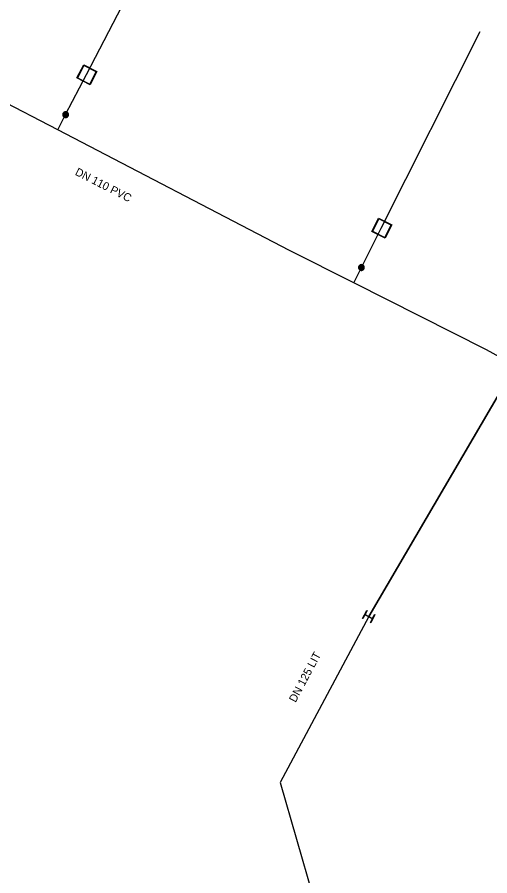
# Model space of a CAD drawing. Extents: x -818065 to -817466, y -1067968 to -1067520.
# Drawn here: x -817769.8 to -817728.5, y -1067828 to -1067753 of the extents above; entities that cross this region are included whole.
import ezdxf

# ---------------------------------------------------------------- set-up
doc = ezdxf.new("R2010")
doc.units = 0
doc.layers.add('Default', color=7, linetype='Continuous')
doc.layers.add('Level 0', color=7, linetype='Continuous')

msp = doc.modelspace()

# ---------------------------------------------------------------- linework, layer by layer
at = {"layer": 'Default'}
for points in [[(-817764.005, -1067757.155), (-817762.847, -1067757.745), (-817763.437, -1067758.903), (-817764.596, -1067758.313), (-817764.005, -1067757.155)], [(-817764.541, -1067758.295), (-817763.455, -1067758.849), (-817762.902, -1067757.763), (-817763.988, -1067757.209), (-817764.541, -1067758.295)], [(-817738.211, -1067770.573), (-817737.053, -1067771.163), (-817737.643, -1067772.321), (-817738.801, -1067771.731), (-817738.211, -1067770.573)], [(-817738.747, -1067771.713), (-817737.661, -1067772.267), (-817737.107, -1067771.181), (-817738.193, -1067770.627), (-817738.747, -1067771.713)], [(-817739.399, -1067805.223), (-817739.581, -1067805.565), (-817739.603, -1067805.554), (-817739.228, -1067804.847), (-817739.206, -1067804.859), (-817739.388, -1067805.201), (-817738.725, -1067805.553), (-817738.543, -1067805.211), (-817738.521, -1067805.223), (-817738.897, -1067805.929), (-817738.919, -1067805.917), (-817738.737, -1067805.575), (-817739.399, -1067805.223)]]:
    msp.add_lwpolyline(points, dxfattribs=at)
for points in [[(-817765.584, -1067761.269), (-817765.521, -1067761.269), (-817765.461, -1067761.301), (-817765.402, -1067761.334), (-817765.368, -1067761.394), (-817765.334, -1067761.454), (-817765.334, -1067761.519), (-817765.334, -1067761.584), (-817765.367, -1067761.644), (-817765.4, -1067761.703), (-817765.459, -1067761.736), (-817765.519, -1067761.769), (-817765.584, -1067761.769), (-817765.649, -1067761.769), (-817765.708, -1067761.736), (-817765.768, -1067761.703), (-817765.801, -1067761.644), (-817765.834, -1067761.584), (-817765.834, -1067761.519), (-817765.834, -1067761.454), (-817765.8, -1067761.394), (-817765.767, -1067761.334), (-817765.707, -1067761.301), (-817765.647, -1067761.269), (-817765.584, -1067761.269)], [(-817765.584, -1067761.293), (-817765.641, -1067761.293), (-817765.696, -1067761.322), (-817765.75, -1067761.351), (-817765.78, -1067761.405), (-817765.81, -1067761.46), (-817765.81, -1067761.519), (-817765.81, -1067761.578), (-817765.781, -1067761.632), (-817765.751, -1067761.686), (-817765.697, -1067761.716), (-817765.643, -1067761.746), (-817765.584, -1067761.746), (-817765.525, -1067761.746), (-817765.471, -1067761.716), (-817765.417, -1067761.686), (-817765.387, -1067761.632), (-817765.357, -1067761.578), (-817765.357, -1067761.519), (-817765.357, -1067761.46), (-817765.388, -1067761.405), (-817765.419, -1067761.351), (-817765.473, -1067761.322), (-817765.527, -1067761.293), (-817765.584, -1067761.293)], [(-817765.584, -1067761.31), (-817765.531, -1067761.31), (-817765.481, -1067761.337), (-817765.431, -1067761.364), (-817765.403, -1067761.414), (-817765.374, -1067761.464), (-817765.374, -1067761.519), (-817765.374, -1067761.574), (-817765.402, -1067761.624), (-817765.429, -1067761.673), (-817765.479, -1067761.701), (-817765.529, -1067761.729), (-817765.584, -1067761.729), (-817765.638, -1067761.729), (-817765.688, -1067761.701), (-817765.738, -1067761.673), (-817765.766, -1067761.624), (-817765.793, -1067761.574), (-817765.793, -1067761.519), (-817765.793, -1067761.464), (-817765.765, -1067761.414), (-817765.737, -1067761.364), (-817765.687, -1067761.337), (-817765.637, -1067761.31), (-817765.584, -1067761.31)], [(-817765.584, -1067761.332), (-817765.663, -1067761.332), (-817765.717, -1067761.387), (-817765.771, -1067761.441), (-817765.771, -1067761.519), (-817765.771, -1067761.597), (-817765.717, -1067761.652), (-817765.662, -1067761.707), (-817765.584, -1067761.707), (-817765.506, -1067761.707), (-817765.451, -1067761.652), (-817765.396, -1067761.597), (-817765.396, -1067761.519), (-817765.396, -1067761.441), (-817765.451, -1067761.387), (-817765.506, -1067761.332), (-817765.584, -1067761.332)], [(-817765.584, -1067761.355), (-817765.516, -1067761.355), (-817765.468, -1067761.403), (-817765.42, -1067761.451), (-817765.42, -1067761.519), (-817765.42, -1067761.587), (-817765.468, -1067761.635), (-817765.516, -1067761.683), (-817765.584, -1067761.683), (-817765.653, -1067761.683), (-817765.701, -1067761.635), (-817765.748, -1067761.587), (-817765.748, -1067761.519), (-817765.748, -1067761.451), (-817765.701, -1067761.403), (-817765.653, -1067761.355), (-817765.584, -1067761.355)], [(-817765.584, -1067761.374), (-817765.644, -1067761.374), (-817765.687, -1067761.417), (-817765.729, -1067761.459), (-817765.729, -1067761.519), (-817765.729, -1067761.578), (-817765.687, -1067761.621), (-817765.644, -1067761.663), (-817765.584, -1067761.663), (-817765.525, -1067761.663), (-817765.482, -1067761.621), (-817765.44, -1067761.578), (-817765.44, -1067761.519), (-817765.44, -1067761.459), (-817765.482, -1067761.417), (-817765.524, -1067761.374), (-817765.584, -1067761.374)], [(-817765.584, -1067761.394), (-817765.532, -1067761.394), (-817765.495, -1067761.431), (-817765.459, -1067761.467), (-817765.459, -1067761.519), (-817765.459, -1067761.571), (-817765.496, -1067761.608), (-817765.532, -1067761.644), (-817765.584, -1067761.644), (-817765.636, -1067761.644), (-817765.672, -1067761.608), (-817765.709, -1067761.571), (-817765.709, -1067761.519), (-817765.709, -1067761.467), (-817765.673, -1067761.431), (-817765.636, -1067761.394), (-817765.584, -1067761.394)], [(-817765.584, -1067761.417), (-817765.626, -1067761.417), (-817765.656, -1067761.447), (-817765.686, -1067761.477), (-817765.686, -1067761.519), (-817765.686, -1067761.561), (-817765.656, -1067761.591), (-817765.626, -1067761.62), (-817765.584, -1067761.62), (-817765.542, -1067761.62), (-817765.512, -1067761.591), (-817765.483, -1067761.561), (-817765.483, -1067761.519), (-817765.483, -1067761.477), (-817765.512, -1067761.447), (-817765.542, -1067761.417), (-817765.584, -1067761.417)], [(-817765.584, -1067761.435), (-817765.549, -1067761.435), (-817765.524, -1067761.459), (-817765.5, -1067761.484), (-817765.5, -1067761.519), (-817765.5, -1067761.554), (-817765.525, -1067761.579), (-817765.549, -1067761.603), (-817765.584, -1067761.603), (-817765.619, -1067761.603), (-817765.644, -1067761.579), (-817765.668, -1067761.554), (-817765.668, -1067761.519), (-817765.668, -1067761.484), (-817765.644, -1067761.459), (-817765.619, -1067761.435), (-817765.584, -1067761.435)], [(-817765.584, -1067761.457), (-817765.61, -1067761.457), (-817765.628, -1067761.475), (-817765.646, -1067761.493), (-817765.646, -1067761.519), (-817765.646, -1067761.545), (-817765.628, -1067761.563), (-817765.61, -1067761.582), (-817765.584, -1067761.582), (-817765.558, -1067761.582), (-817765.54, -1067761.563), (-817765.521, -1067761.545), (-817765.521, -1067761.519), (-817765.521, -1067761.493), (-817765.54, -1067761.475), (-817765.558, -1067761.457), (-817765.584, -1067761.457)], [(-817765.584, -1067761.48), (-817765.568, -1067761.48), (-817765.556, -1067761.491), (-817765.545, -1067761.503), (-817765.545, -1067761.519), (-817765.545, -1067761.535), (-817765.556, -1067761.547), (-817765.568, -1067761.558), (-817765.584, -1067761.558), (-817765.6, -1067761.558), (-817765.612, -1067761.547), (-817765.623, -1067761.535), (-817765.623, -1067761.519), (-817765.623, -1067761.503), (-817765.612, -1067761.491), (-817765.6, -1067761.48), (-817765.584, -1067761.48)], [(-817765.584, -1067761.496), (-817765.594, -1067761.496), (-817765.601, -1067761.502), (-817765.608, -1067761.509), (-817765.608, -1067761.519), (-817765.608, -1067761.529), (-817765.601, -1067761.536), (-817765.594, -1067761.543), (-817765.584, -1067761.543), (-817765.574, -1067761.543), (-817765.567, -1067761.536), (-817765.561, -1067761.529), (-817765.561, -1067761.519), (-817765.561, -1067761.509), (-817765.567, -1067761.502), (-817765.574, -1067761.496), (-817765.584, -1067761.496)], [(-817739.708, -1067774.628), (-817739.645, -1067774.628), (-817739.585, -1067774.66), (-817739.525, -1067774.692), (-817739.491, -1067774.752), (-817739.457, -1067774.812), (-817739.457, -1067774.878), (-817739.457, -1067774.943), (-817739.49, -1067775.002), (-817739.523, -1067775.062), (-817739.583, -1067775.095), (-817739.642, -1067775.128), (-817739.708, -1067775.128), (-817739.772, -1067775.128), (-817739.832, -1067775.095), (-817739.891, -1067775.062), (-817739.924, -1067775.002), (-817739.957, -1067774.943), (-817739.957, -1067774.878), (-817739.957, -1067774.812), (-817739.924, -1067774.752), (-817739.89, -1067774.692), (-817739.831, -1067774.66), (-817739.771, -1067774.628), (-817739.708, -1067774.628)], [(-817739.708, -1067774.651), (-817739.765, -1067774.651), (-817739.819, -1067774.68), (-817739.873, -1067774.709), (-817739.904, -1067774.764), (-817739.934, -1067774.819), (-817739.934, -1067774.878), (-817739.934, -1067774.937), (-817739.904, -1067774.991), (-817739.874, -1067775.044), (-817739.82, -1067775.074), (-817739.766, -1067775.104), (-817739.708, -1067775.104), (-817739.649, -1067775.104), (-817739.594, -1067775.074), (-817739.54, -1067775.044), (-817739.511, -1067774.991), (-817739.481, -1067774.937), (-817739.481, -1067774.878), (-817739.481, -1067774.819), (-817739.512, -1067774.764), (-817739.542, -1067774.709), (-817739.596, -1067774.68), (-817739.65, -1067774.651), (-817739.708, -1067774.651)], [(-817739.708, -1067774.668), (-817739.655, -1067774.668), (-817739.605, -1067774.695), (-817739.555, -1067774.722), (-817739.526, -1067774.773), (-817739.498, -1067774.823), (-817739.498, -1067774.878), (-817739.498, -1067774.932), (-817739.525, -1067774.982), (-817739.553, -1067775.032), (-817739.603, -1067775.06), (-817739.653, -1067775.087), (-817739.708, -1067775.087), (-817739.762, -1067775.087), (-817739.812, -1067775.06), (-817739.862, -1067775.032), (-817739.889, -1067774.982), (-817739.917, -1067774.932), (-817739.917, -1067774.878), (-817739.917, -1067774.823), (-817739.889, -1067774.773), (-817739.861, -1067774.722), (-817739.811, -1067774.695), (-817739.76, -1067774.668), (-817739.708, -1067774.668)], [(-817739.708, -1067774.69), (-817739.786, -1067774.69), (-817739.84, -1067774.745), (-817739.895, -1067774.8), (-817739.895, -1067774.878), (-817739.895, -1067774.956), (-817739.84, -1067775.01), (-817739.785, -1067775.065), (-817739.708, -1067775.065), (-817739.63, -1067775.065), (-817739.575, -1067775.01), (-817739.52, -1067774.956), (-817739.52, -1067774.878), (-817739.52, -1067774.8), (-817739.574, -1067774.745), (-817739.629, -1067774.69), (-817739.708, -1067774.69)], [(-817739.708, -1067774.713), (-817739.639, -1067774.713), (-817739.592, -1067774.761), (-817739.544, -1067774.809), (-817739.544, -1067774.877), (-817739.544, -1067774.945), (-817739.592, -1067774.993), (-817739.64, -1067775.041), (-817739.708, -1067775.041), (-817739.776, -1067775.041), (-817739.824, -1067774.993), (-817739.872, -1067774.945), (-817739.872, -1067774.877), (-817739.872, -1067774.809), (-817739.824, -1067774.761), (-817739.776, -1067774.713), (-817739.708, -1067774.713)], [(-817739.708, -1067774.733), (-817739.768, -1067774.733), (-817739.81, -1067774.775), (-817739.852, -1067774.817), (-817739.852, -1067774.877), (-817739.852, -1067774.937), (-817739.81, -1067774.979), (-817739.768, -1067775.021), (-817739.708, -1067775.021), (-817739.648, -1067775.021), (-817739.606, -1067774.979), (-817739.564, -1067774.937), (-817739.564, -1067774.877), (-817739.564, -1067774.817), (-817739.606, -1067774.775), (-817739.648, -1067774.733), (-817739.708, -1067774.733)], [(-817739.708, -1067774.753), (-817739.655, -1067774.753), (-817739.619, -1067774.789), (-817739.582, -1067774.826), (-817739.582, -1067774.878), (-817739.582, -1067774.93), (-817739.619, -1067774.966), (-817739.656, -1067775.003), (-817739.708, -1067775.003), (-817739.759, -1067775.003), (-817739.796, -1067774.966), (-817739.832, -1067774.93), (-817739.832, -1067774.878), (-817739.832, -1067774.826), (-817739.796, -1067774.789), (-817739.76, -1067774.753), (-817739.708, -1067774.753)], [(-817739.708, -1067774.776), (-817739.75, -1067774.776), (-817739.78, -1067774.806), (-817739.809, -1067774.835), (-817739.809, -1067774.877), (-817739.809, -1067774.92), (-817739.78, -1067774.949), (-817739.75, -1067774.979), (-817739.708, -1067774.979), (-817739.666, -1067774.979), (-817739.636, -1067774.949), (-817739.606, -1067774.92), (-817739.606, -1067774.877), (-817739.606, -1067774.835), (-817739.636, -1067774.806), (-817739.665, -1067774.776), (-817739.708, -1067774.776)], [(-817739.708, -1067774.793), (-817739.672, -1067774.793), (-817739.648, -1067774.818), (-817739.623, -1067774.842), (-817739.623, -1067774.877), (-817739.623, -1067774.913), (-817739.648, -1067774.937), (-817739.673, -1067774.962), (-817739.708, -1067774.962), (-817739.743, -1067774.962), (-817739.767, -1067774.937), (-817739.792, -1067774.913), (-817739.792, -1067774.877), (-817739.792, -1067774.842), (-817739.767, -1067774.818), (-817739.743, -1067774.793), (-817739.708, -1067774.793)], [(-817739.708, -1067774.815), (-817739.733, -1067774.815), (-817739.752, -1067774.833), (-817739.77, -1067774.852), (-817739.77, -1067774.878), (-817739.77, -1067774.904), (-817739.752, -1067774.922), (-817739.733, -1067774.94), (-817739.708, -1067774.94), (-817739.681, -1067774.94), (-817739.663, -1067774.922), (-817739.645, -1067774.904), (-817739.645, -1067774.878), (-817739.645, -1067774.852), (-817739.663, -1067774.833), (-817739.681, -1067774.815), (-817739.708, -1067774.815)], [(-817739.708, -1067774.839), (-817739.691, -1067774.839), (-817739.68, -1067774.85), (-817739.669, -1067774.861), (-817739.669, -1067774.878), (-817739.669, -1067774.894), (-817739.68, -1067774.905), (-817739.691, -1067774.917), (-817739.708, -1067774.917), (-817739.724, -1067774.917), (-817739.735, -1067774.905), (-817739.747, -1067774.894), (-817739.747, -1067774.878), (-817739.747, -1067774.861), (-817739.735, -1067774.85), (-817739.724, -1067774.839), (-817739.708, -1067774.839)], [(-817739.708, -1067774.854), (-817739.717, -1067774.854), (-817739.724, -1067774.861), (-817739.731, -1067774.868), (-817739.731, -1067774.878), (-817739.731, -1067774.887), (-817739.724, -1067774.894), (-817739.717, -1067774.901), (-817739.708, -1067774.901), (-817739.698, -1067774.901), (-817739.691, -1067774.894), (-817739.684, -1067774.887), (-817739.684, -1067774.878), (-817739.684, -1067774.868), (-817739.691, -1067774.861), (-817739.698, -1067774.854), (-817739.708, -1067774.854)]]:
    msp.add_open_spline(points, degree=3, dxfattribs=at)
at = {"layer": 'Level 0'}
for p, q in [((-817763.763, -1067758.013), (-817751.347, -1067734.113)), ((-817737.968, -1067771.431), (-817729.305, -1067754.261)), ((-817765.584, -1067761.519), (-817763.763, -1067758.013)), ((-817766.276, -1067762.85), (-817773.173, -1067759.267)), ((-817766.276, -1067762.85), (-817765.584, -1067761.519)), ((-817746.009, -1067773.378), (-817766.276, -1067762.85)), ((-817739.708, -1067774.877), (-817737.968, -1067771.431)), ((-817740.383, -1067776.217), (-817746.009, -1067773.378)), ((-817740.383, -1067776.217), (-817739.708, -1067774.877)), ((-817728.777, -1067782.073), (-817740.383, -1067776.217)), ((-817724.16, -1067779.91), (-817739.07, -1067805.39)), ((-817739.07, -1067805.39), (-817724.16, -1067779.91)), ((-817727.322, -1067782.861), (-817728.777, -1067782.073)), ((-817739.07, -1067805.39), (-817746.81, -1067819.9)), ((-817746.81, -1067819.9), (-817741.25, -1067839.13))]:
    msp.add_line(p, q, dxfattribs=at)

# ---------------------------------------------------------------- texts
for s, rotation, p in [('DN 110 PVC', 333, (-817764.822, -1067766.751)), ('DN 125 LIT', 62, (-817745.468, -1067812.948))]:
    msp.add_text(s, height=0.7, rotation=rotation, dxfattribs=at).set_placement(p)

doc.saveas('drawing.dxf')
